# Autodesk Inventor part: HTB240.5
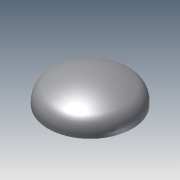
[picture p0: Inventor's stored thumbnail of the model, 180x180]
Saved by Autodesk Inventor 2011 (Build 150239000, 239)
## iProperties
Created: 2010-05
Part Number: HTB240.5
Document SubType Name: Modeling
Designer: mklassen
Density: 1 g/cm^3
Description: HEAD TORISPHERICAL 0.8 24"x 0.5"
THK: 0.500 in
OD: 24.000 in
LIP: 1.000 in
DRFAC: 0.850 ul
KRFAC: 0.154 ul
Author: mklassen
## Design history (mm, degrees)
sketch "skConical"
  geometry: L1 (0, -94.768)-(0, 568.606) reference; L2 (-104.131, 0)-(376.544, 0) reference; L3 (292.1, 0)-(292.1, 25.4); L4 (275.392, 78.859)-(20.88, 446.264); L5 (0, 457.2)-(-35.463, 457.2); L6 (31.319, 453.496)-(285.832, 86.091); L7 (304.8, 25.4)-(304.8, 0); L8 (292.1, 0)-(304.8, 0); L9 (0, 457.2)-(0, 469.9); A1 r 93.878 centre (198.222, 25.4) between (292.1, 25.4) and (275.392, 78.859); A2 r 25.4 centre (0, 431.8) between (20.88, 446.264) and (0, 457.2); A3 r 38.1 centre (0, 431.8) between (31.319, 453.496) and (0, 469.9); A4 r 106.578 centre (198.222, 25.4) between (304.8, 25.4) and (285.832, 86.091); 1 further point
  constraints: 14 end point, 8 point on circle, 4 centre point, 4 tangent, 2 perpendicular, 2 point on line, 1 collinear, 1 horizontal, 3 other
  dimensions: "d6" = 93.8784 radius of A1 (derived); "d7" = 12.7 distance between parallel lines of L7 L3 (derived); "d8" = 25.4 distance of L3.start L3.end (= LIP); "d9" = 609.6 diameter of L7 L1 (derived); "d10" = 457.2 distance between parallel lines of L5 L2 (derived); "d11" = 25.4 radius of A2
revolve "Conical" sketch "skConical" stored, may be unused: angle "d12" = 90 deg
sketch "skDiffuser"
  geometry: L1 (0, -266.355)-(0, 624.896) reference; L2 (-62.91, 0)-(377.459, 0) reference; L3 (292.1, 0)-(292.1, 142.234); L4 (292.1, 0)-(304.8, 0); L5 (0, -143.029)-(0, -155.729); A1 r 93.878 centre (198.222, 0) between (242.081, -83.003) and (292.1, 0); A2 r 518.16 centre (0, 375.131) between (0, -143.029) and (242.081, -83.003); A3 r 530.86 centre (0, 375.131) between (0, -155.729) and (248.014, -94.232); A4 r 106.578 centre (198.222, 0) between (248.014, -94.232) and (304.8, 0); 1 further point
  constraints: 8 point on circle, 6 end point, 4 centre point, 3 point on line, 2 perpendicular, 2 tangent, 1 collinear, 1 other
  dimensions: "d15" = 93.8784 radius of A1 (derived); "d16" = 518.16 radius of A2 (derived); "d17" = 12.7 distance of L3.start L4.end (derived); "d18" = 609.6 diameter of L4.end L1 (derived)
revolve "Diffuser" sketch "skDiffuser" stored, may be unused: angle "d19" = 90 deg
sketch "skEllipsoidal"
  geometry: L1 (-73.371, 0)-(397.287, 0) reference; L2 (0, -42.808)-(0, 243.852) reference; L3 (292.1, 0)-(304.8, 0); L4 (0, 139.7)-(0, 152.4); 2 further points; 1 other entity
  constraints: 4 end point, 2 point on line, 1 coincident, 1 collinear, 1 horizontal, 1 perpendicular, 7 other
  dimensions: "d22" = 609.6 diameter of L3.end L2 (derived); "d23" = 152.4 distance from line of L4.end L1 (derived); "d24" = 12.7 distance of L3.start L3.end (derived)
revolve "Ellipsoidal" sketch "skEllipsoidal" stored, may be unused: angle "d25" = 90 deg
sketch "skFlat"
  geometry: L1 (-64.011, 0)-(384.067, 0) reference; L2 (0, -22.863)-(0, 137.179) reference; L3 (304.8, 0)-(304.8, 25.4); L4 (198.222, 131.978)-(0, 131.978); L5 (0, 119.278)-(198.222, 119.278); L6 (292.1, 25.4)-(292.1, 0); L7 (0, 119.278)-(0, 131.978); L8 (292.1, 0)-(304.8, 0); A1 r 106.578 centre (198.222, 25.4) between (304.8, 25.4) and (198.222, 131.978); A2 r 93.878 centre (198.222, 25.4) between (292.1, 25.4) and (198.222, 119.278); 1 further point
  constraints: 12 end point, 4 point on circle, 2 centre point, 2 perpendicular, 2 point on line, 2 tangent, 1 collinear, 1 parallel, 2 other
  dimensions: "d28" = 609.6 diameter of L3 L2 (derived); "d31" = 93.8784 radius of A2 (derived); "d32" = 12.7 distance of L6.end L3.start (derived); "d33" = 25.4 distance of L6.start L6.end (= LIP)
revolve "Flat" sketch "skFlat" stored, may be unused: angle "d34" = 90 deg
sketch "skHemispherical"
  geometry: L1 (0, -73.585)-(0, 441.511) reference; L2 (-73.585, 0)-(441.511, 0) reference; L3 (292.1, 0)-(304.8, 0); L4 (0, 292.1)-(0, 304.8); A1 r 304.8 centre (0, 0) between (304.8, 0) and (0, 304.8); A2 r 292.1 centre (0, 0) between (292.1, 0) and (0, 292.1); 1 further point
  constraints: 5 point on circle, 4 end point, 2 centre point, 2 collinear, 2 point on line, 1 coincident
  dimensions: "d37" = 609.6 diameter of L3.end L1 (derived); "d38" = 12.7 distance of L3.start L3.end (derived)
revolve "Hemispherical" sketch "skHemispherical" stored, may be unused: angle "d39" = 90 deg
sketch "skTorispherical"
  geometry: L1 (-62.91, 0)-(377.459, 0) reference; L2 (0, -599.496)-(0, 291.755) reference; L3 (292.1, 0)-(292.1, 25.4); L4 (304.8, 25.4)-(304.8, 0); L5 (292.1, 0)-(304.8, 0); L6 (0, 168.429)-(0, 181.129); A1 r 93.878 centre (198.222, 25.4) between (292.1, 25.4) and (242.081, 108.403); A2 r 518.16 centre (0, -349.731) between (242.081, 108.403) and (0, 168.429); A3 r 530.86 centre (0, -349.731) between (248.014, 119.632) and (0, 181.129); A4 r 106.578 centre (198.222, 25.4) between (304.8, 25.4) and (248.014, 119.632); 1 further point
  constraints: 8 end point, 8 point on circle, 4 centre point, 2 perpendicular, 2 point on line, 2 tangent, 1 collinear, 1 vertical alignment, 2 other
  dimensions: "d43" = 25.4 distance of L3.start L3.end (= LIP); "d44" = 93.8784 radius of A1 (derived); "d45" = 518.16 radius of A2 (derived); "d46" = 12.7 distance of L3.start L4.end (derived); "d47" = 609.6 diameter of L4 L2 (derived)
revolve "Torispherical" sketch "skTorispherical" stored, may be unused: angle "d48" = 90 deg
body "Solid1"
other parameters: "LIP" = 25.4 [user parameter; used in 3 equation terms], "DRFAC" = 0.85 [user parameter; used in 2 equation terms], "KRFAC" = 0.154 [user parameter; used in 4 equation terms], "d13" = 0, "d14" = 0, "d20" = 0, "d21" = 0, "d26" = 0, "d27" = 0, "d35" = 0, "d36" = 0, "d40" = 0, "d41" = 0, "d49" = 0, "d50" = 0, "d51" = 0, "d52" = 0
